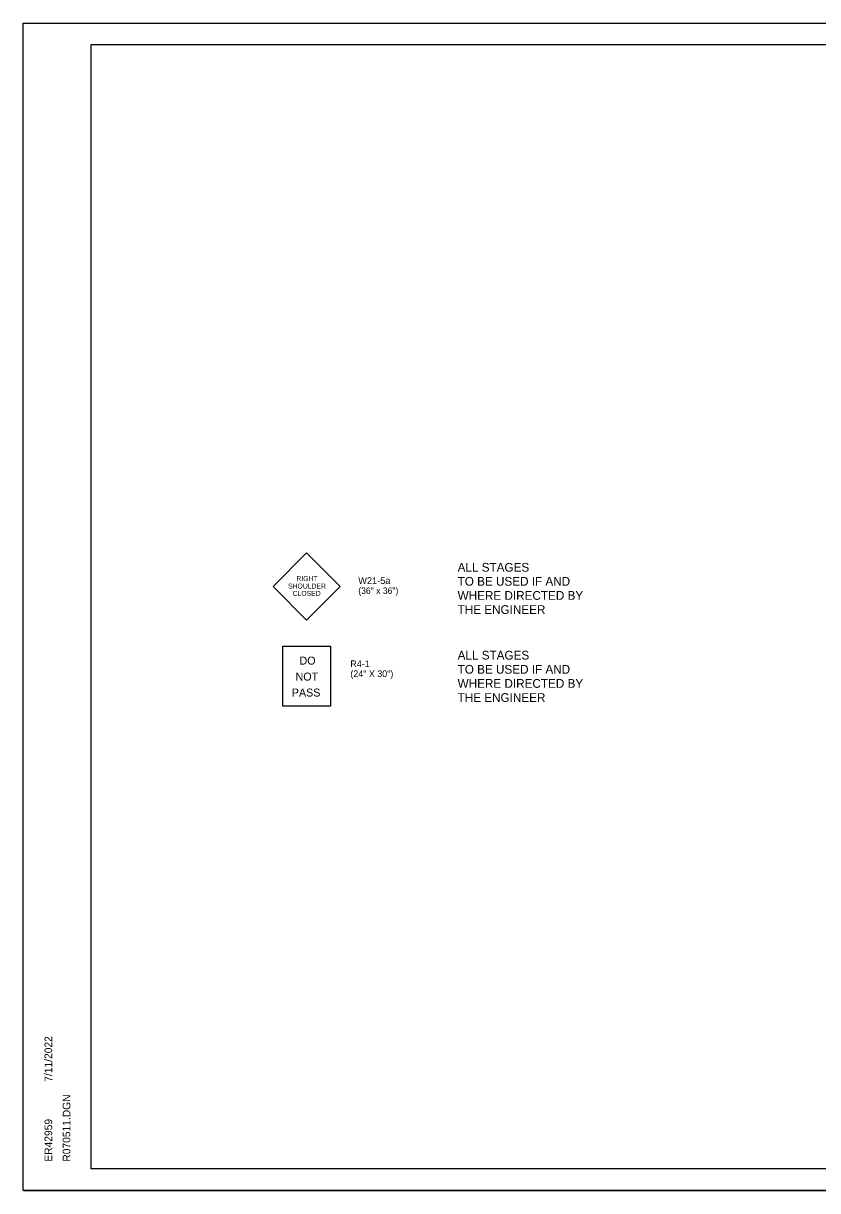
# Model space of a CAD drawing. Extents: x 1398460 to 1408037, y 380768 to 383968.
# Drawn here: x 1402332 to 1403058, y 382901 to 383968 of the extents above; entities that cross this region are included whole.
import ezdxf

# ---------------------------------------------------------------- set-up
doc = ezdxf.new("R2010")
doc.units = 0
for name, color, linetype in [('R_Border', 7, 'Continuous'), ('R_Dimension', 7, 'Continuous'), ('R_MOT', 7, 'Continuous'), ('R_No Plot', 7, 'Continuous')]:
    doc.layers.add(name, color=color, linetype=linetype)

msp = doc.modelspace()

# ---------------------------------------------------------------- linework, layer by layer
at = {"layer": 'R_Border'}
for p, q in [((1402394.3, 383948.1), (1403975.2, 383948.1)), ((1402394.3, 382920.8), (1402394.3, 383948.1)), ((1402394.3, 382920.8), (1402394.3, 382920.8)), ((1403975.2, 382920.8), (1402394.3, 382920.8))]:
    msp.add_line(p, q, dxfattribs=at)
at = {"layer": 'R_MOT'}
for p, q in [((1402591.1, 383483.6), (1402560.5, 383453)), ((1402621.8, 383453), (1402591.1, 383483.6)), ((1402591.1, 383422.3), (1402560.5, 383453)), ((1402621.8, 383453), (1402591.1, 383422.3))]:
    msp.add_line(p, q, dxfattribs=at)
msp.add_lwpolyline([(1402612.9, 383398.4), (1402612.9, 383343.5), (1402569.3, 383343.5), (1402569.3, 383398.4)], close=True, dxfattribs=at)
at = {"layer": 'R_No Plot'}
for p, q in [((1402332.3, 383967.6), (1403998.9, 383967.6)), ((1402332.3, 382900.9), (1403998.9, 382900.9))]:
    msp.add_line(p, q, dxfattribs=at)
for points in [[(1402332.2, 383967.6), (1403998.9, 383967.6), (1403998.9, 382900.9), (1402332.2, 382900.9)], [(1403563.9, 383948.1), (1403662, 383948.1), (1403662, 383898.7), (1403742.5, 383898.7), (1403858.5, 383898.7), (1403858.5, 383777), (1403975.2, 383777), (1403975.2, 382920.8), (1402394.3, 382920.8), (1402394.3, 383948.1)]]:
    msp.add_lwpolyline(points, close=True, dxfattribs=at)

# ---------------------------------------------------------------- texts
at = {"layer": 'R_Border'}
for s, p in [('7/11/2022', (1402358.6, 383000.4)), ('R070511.DGN', (1402375.2, 382927.4)), ('ER42959', (1402358.6, 382927.4))]:
    msp.add_text(s, height=7, rotation=90, dxfattribs=at).set_placement(p)
at = {"layer": 'R_Dimension'}
for s, p in [('ALL STAGES', (1402729.1, 383466.5)), ('TO BE USED IF AND', (1402729.1, 383453.7)), ('WHERE DIRECTED BY', (1402729.1, 383440.8)), ('THE ENGINEER', (1402729.1, 383427.9)), ('ALL STAGES', (1402729.1, 383386.2)), ('TO BE USED IF AND', (1402729.1, 383373.3)), ('WHERE DIRECTED BY', (1402729.1, 383360.4)), ('THE ENGINEER', (1402729.1, 383347.5))]:
    msp.add_text(s, height=8, rotation=360, dxfattribs=at).set_placement(p)
at = {"layer": 'R_MOT'}
for s, height, rotation, p in [('RIGHT', 4.52, 0.0004, (1402581.7, 383457.9)), ('SHOULDER', 4.52, 0, (1402574.1, 383451.1)), ('CLOSED', 4.52, 0.0006, (1402578.3, 383444.4)), ('DO', 7.31, 360, (1402584.6, 383381.6)), ('R4-1', 6.08, 360, (1402631.1, 383379.3)), ('(24" X 30")', 6.084, 360, (1402631.1, 383370.2)), ('NOT', 7.31, 360, (1402581, 383367)), ('PASS', 7.31, 360, (1402577.6, 383352.4))]:
    msp.add_text(s, height=height, rotation=rotation, dxfattribs=at).set_placement(p)
for s, height, p in [('W21-5a', 6.27, (1402638.3, 383455.2)), ('(36" x 36")', 5.88, (1402638.3, 383446.2))]:
    msp.add_text(s, height=height, dxfattribs=at).set_placement(p)

doc.saveas('drawing.dxf')
